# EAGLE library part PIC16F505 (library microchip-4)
MICROCONTROLLER 1k Program Flash memory 72 bytes SRAM 12 I/O One 8-bit timer (TMR0) Precision 4 MHz internal oscillator
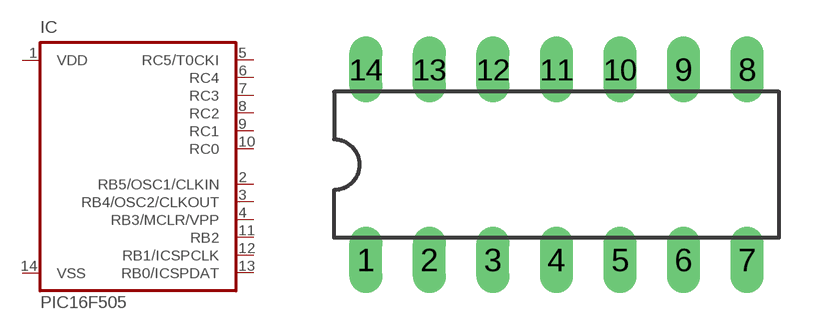
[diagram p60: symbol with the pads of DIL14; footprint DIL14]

Designator prefix IC

## PIC16F505  [DIL14]
1  VDD  pwr
2  RB5/OSC1/CLKIN
3  RB4/OSC2/CLKOUT
4  RB3/MCLR/VPP
5  RC5/T0CKI
6  RC4
7  RC3
8  RC2
9  RC1
10  RC0
11  RB2
12  RB1/ICSPCLK
13  RB0/ICSPDAT
14  VSS  pwr

## Footprint DIL14 (pad centres in mm)
Dual In Line Package
drill 0.813 long: 1 -7.62,-3.81; 2 -5.08,-3.81; 3 -2.54,-3.81; 4 0,-3.81; 5 2.54,-3.81; 6 5.08,-3.81; 7 7.62,-3.81; 8 7.62,3.81; 9 5.08,3.81; 10 2.54,3.81; 11 0,3.81; 12 -2.54,3.81; 13 -5.08,3.81; 14 -7.62,3.81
